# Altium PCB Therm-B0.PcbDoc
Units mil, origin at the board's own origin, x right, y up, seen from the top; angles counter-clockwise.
Board outline 1600 x 800 mil, 2 copper layers (Top Layer, Bottom Layer); 23 components, 22 nets, 79 pads, 19 vias.
Unrouted connection lines stored in the file: 16.
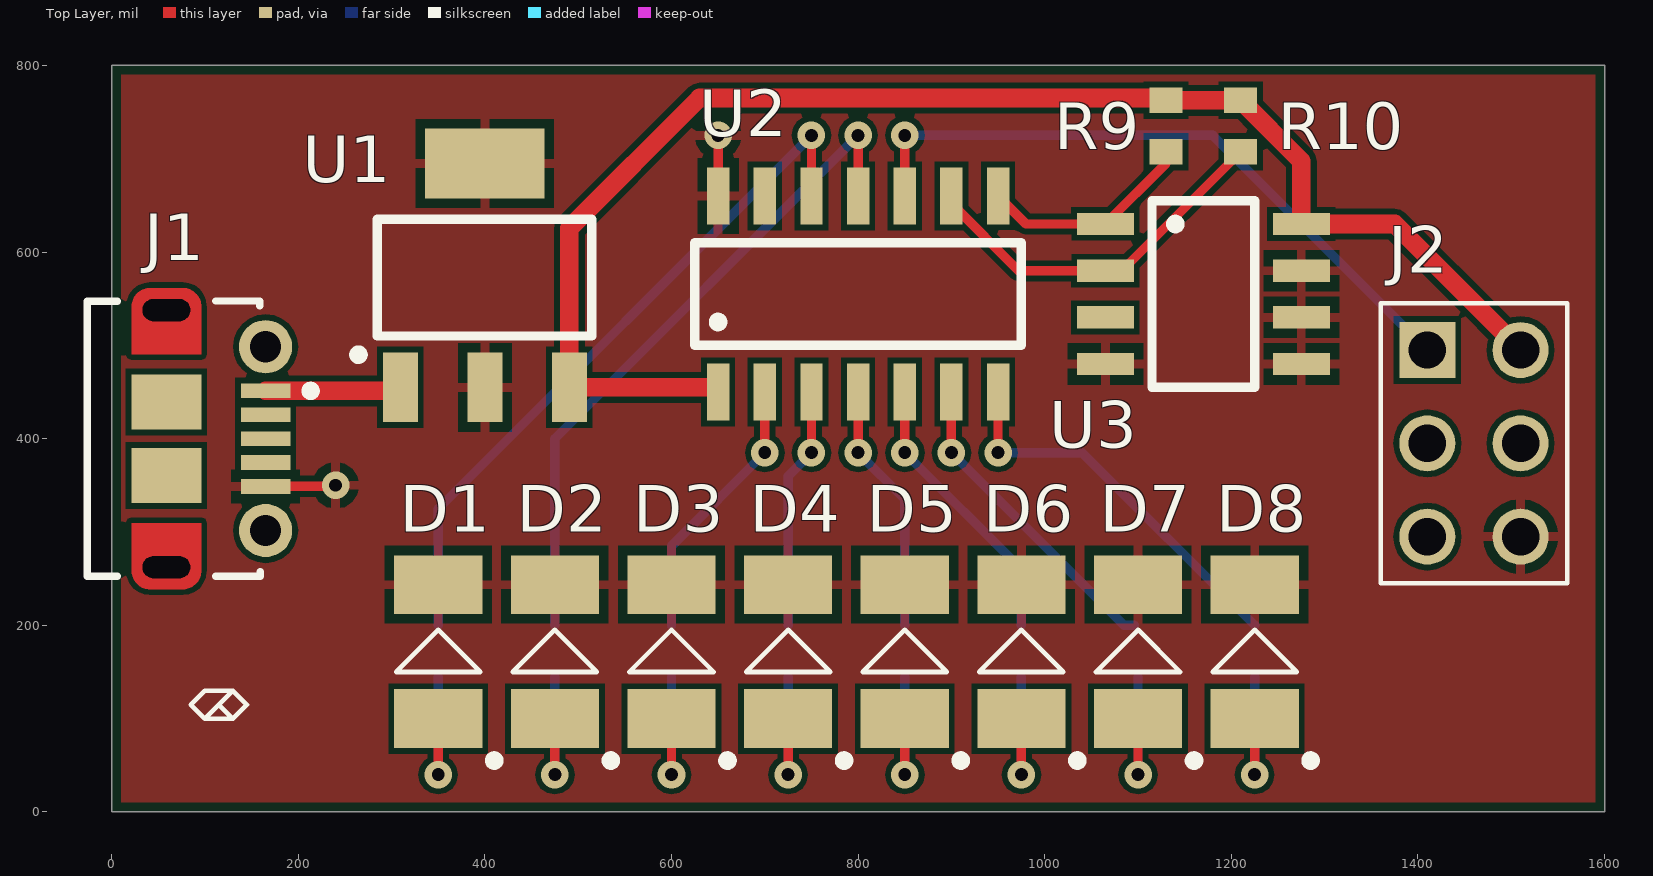
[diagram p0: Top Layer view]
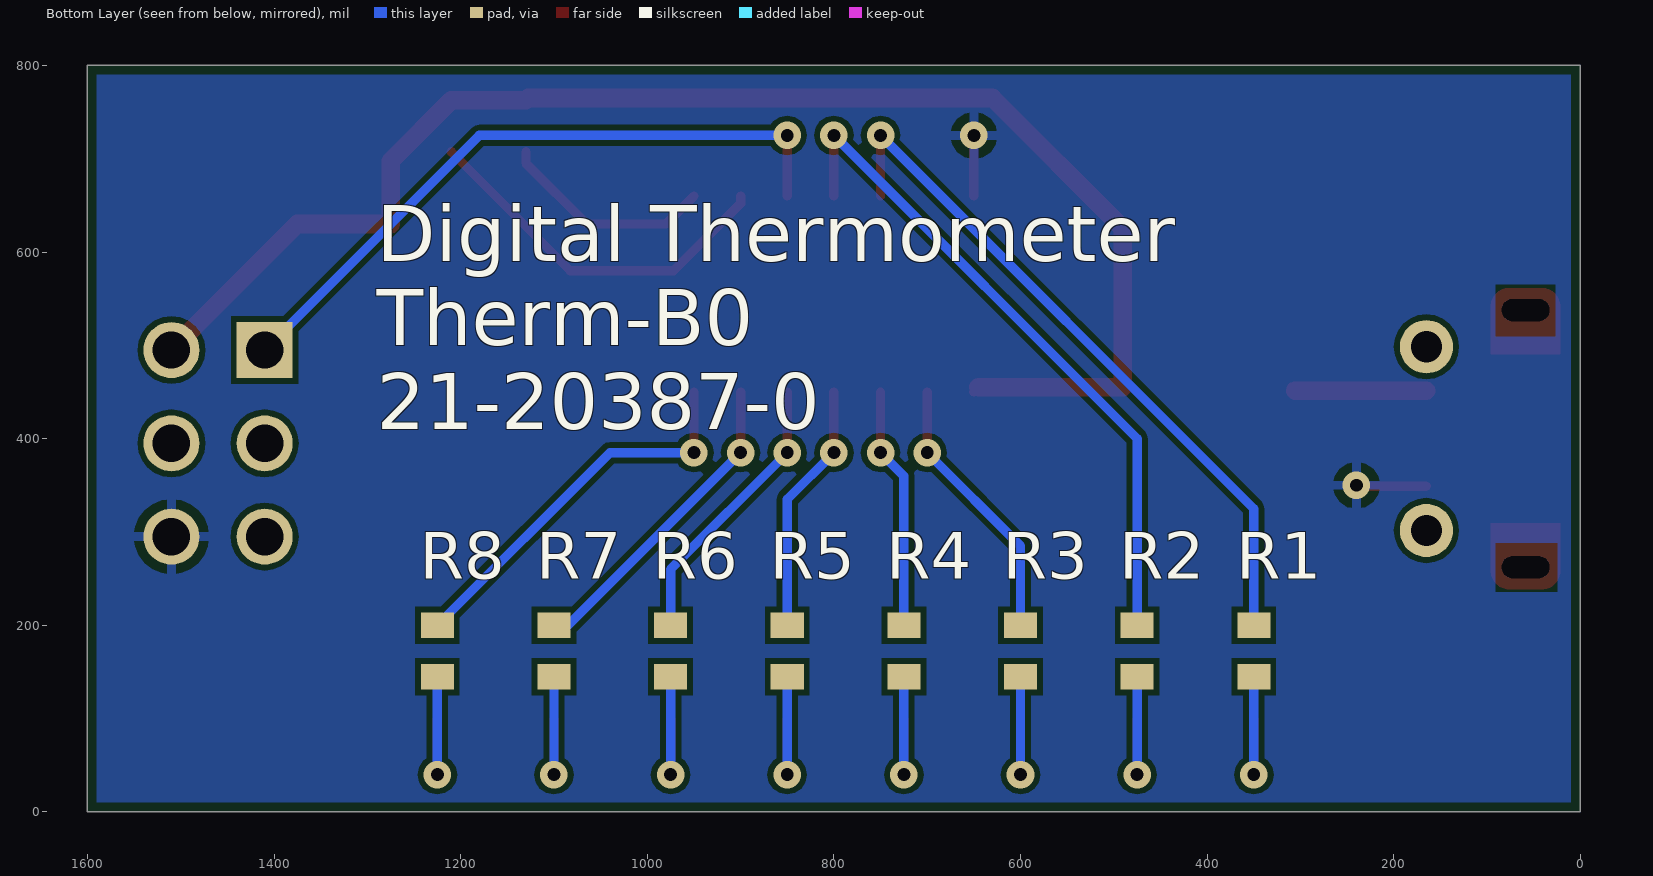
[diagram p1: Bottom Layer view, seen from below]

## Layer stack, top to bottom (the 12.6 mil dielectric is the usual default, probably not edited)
Top Solder: solder mask 0.4, Solder Resist, Dk 3.5
Top Layer: signal copper 1.4
Dielectric 1: dielectric 12.6, FR-4, Dk 4.8
Bottom Layer: signal copper 1.4
Bottom Solder: solder mask 0.4, Solder Resist, Dk 3.5

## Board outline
0,0 1600,0 1600,800 0,800

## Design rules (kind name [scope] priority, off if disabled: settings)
BoardOutlineClearance [All] p1: gap=10 ignorepadtopadclearanceinfootprint=FALSE except(0: Arc-SplitContinuation Track-SplitContinuation SMDPad-SplitContinuation THPad-SplitContinuation Via-SplitContinuation Fill-SplitContinuation Poly-SplitContinuation Region-SplitContinuation Text-SplitContinuation)
Clearance [All] p1: gap=6 ignorepadtopadclearanceinfootprint=FALSE except(0: Arc-Hole Track-Hole SMDPad-Hole THPad-Hole Via-Hole Fill-Hole Poly-Hole Region-Hole Text-Hole)
ComponentClearance [All] p1: gap=1 collisioncheckmode=3 verticalgap=1 showdistances=FALSE
PolygonConnect [All] p1: connectstyle=Relief reliefconductorwidth=10 reliefentries=4 polygonreliefangle="90 Angle" airgapwidth=10
RoutingVias [All] p1: holewidth=28 width=50 viastyle="Through Hole" minholewidth=13.78 minwidth=29.53 maxholewidth=28 maxwidth=29.53
SolderMaskExpansion [All] p1: expansion=4
Width [All] p1: maxlimit=20 minlimit=10 preferedwidth=10 minimp=50.000000 maximp=50.000000 favimp=50.000000
29 further rules are at their usual default settings.

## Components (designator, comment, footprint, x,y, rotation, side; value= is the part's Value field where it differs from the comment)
D1 "LED" LED 350,100 r90 top
D2 "LED" LED 475,100 r90 top
D3 "LED" LED 600,100 r90 top
D4 "LED" LED 725,100 r90 top
D5 "LED" LED 850,100 r90 top
D6 "LED" LED 975,100 r90 top
D7 "LED" LED 1100,100 r90 top
D8 "LED" LED 1225,100 r90 top
J1 "105017-0001" USB-MICRO-B_V 111.85,400 r270 top
J2 "Header" "2x3 Header Straight Pin ZigZag" 1410,495 r0 top
R1 "332" RESC1608X55X25NL10T15 350,172.44 r90 bottom
R2 "332" RESC1608X55X25NL10T15 475,172.44 r90 bottom
R3 "332" RESC1608X55X25NL10T15 600,172.44 r90 bottom
R4 "332" RESC1608X55X25NL10T15 725,172.44 r90 bottom
R5 "332" RESC1608X55X25NL10T15 850,172.44 r90 bottom
R6 "332" RESC1608X55X25NL10T15 975,172.44 r90 bottom
R7 "332" RESC1608X55X25NL10T15 1100,172.44 r90 bottom
R8 "332" RESC1608X55X25NL10T15 1225,172.44 r90 bottom
R9 "2k" RESC1608X55X25NL10T15 1130,735 r90 top
R10 "2k" RESC1608X55X25NL10T15 1210,735 r90 top
U1 "MCP1825S" SOT-223-3 309.5,455 r90 top
U2 "ATtiny404" "14-PIN SOIC 150" 650,450 r90 top
U3 "TMP75B-Q1" "8-Pin SOIC 150" 1065,630 r0 top

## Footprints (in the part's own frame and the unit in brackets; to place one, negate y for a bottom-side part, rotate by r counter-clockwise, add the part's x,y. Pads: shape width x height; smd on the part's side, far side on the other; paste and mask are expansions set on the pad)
"2x3 Header Straight Pin ZigZag" [mil]
  rect 60x60 hole 40: 1(0,0)
  round 60 hole 40: 2(100,0) 3(0,-100) 4(100,-100) 5(0,-200) 6(100,-200)
  silkscreen extent -50,-250 150,50
"8-Pin SOIC 150" [mil]
  rect 61x24 smd: 1(0,0) 2(0,-50) 3(0,-100) 4(0,-150) 5(210,-150) 6(210,-100) 7(210,-50) 8(210,0)
  silkscreen extent 50,-175 160,25
"14-PIN SOIC 150" [mil]
  rect 61x24 smd: 1(0,0) 2(0,-50) 3(0,-100) 4(0,-150) 5(0,-200) 6(0,-250) 7(0,-300) 8(210,-300) 9(210,-250) 10(210,-200) 11(210,-150) 12(210,-100) 13(210,-50) 14(210,0)
  silkscreen extent 50,-325 160,25
LED [mm]
  rect 1.6x2.4 smd: 1(0,0) 2(3.645,0)
  silkscreen extent -1.27,-1.65 2.41,1.14
RESC1608X55X25NL10T15 [mm] "Chip Resistor, 2-Leads, Body 1.60x0.80mm, IPC Medium Density"
  rect 0.7x0.9 smd: 1(-0.7,0) 2(0.7,0)
  body extent -0.85,-0.45 0.85,0.45, height 0.55
SOT-223-3 [mm]
  rect 1.9x0.95 smd: 1(0,0) 2(0,-2.299) 3(0,-4.597)
  rect 1.9x3.25 smd: 4(6.096,-2.299)
  silkscreen extent 0.76,-5.21 4.57,1.27
USB-MICRO-B_V [mm] "USB, MICRO B, Body 7.491x4.695 mm, Pitch 0.65 mm"
  rect 0.4x1.35 smd: 1(-1.3,1.35) 5(1.3,1.35)
  rect 0.4x1.35 smd mask+0.102: 2(-0.65,1.35) 3(0,1.35) 4(0.65,1.35)
  round 1.45 hole 0.85: 6(-2.5,1.35) 7(2.5,1.35)
  rrect50% 0x0 hole 0.6 slot 1.3 at 90 deg: 8(-3.5,-1.35) 11(3.5,-1.35)
  rect 1.5x1.9 smd: 9(-1,-1.35) 10(1,-1.35)
  Top Layer circle w0.5: c-3.6,-1.8 r0.25
  Top Layer circle w0.5: c-3.6,-0.9 r0.25
  Top Layer circle w0.5: c3.6,-1.8 r0.25
  Top Layer circle w0.5: c3.6,-0.9 r0.25
  Top Layer region: -3.6,-1.8 -3.6,-0.9 -4.1,-0.9 -4.1,-1.8
  Top Layer region: 3.6,-0.9 3.6,-1.8 4.1,-1.8 4.1,-0.9
  Top Layer region: 2.3,-0.4 2.3,-2.3 3.6,-2.3 3.6,-0.4
  Top Layer region: -2.3,-2.3 -2.3,-0.4 -3.6,-0.4 -3.6,-2.3
  silkscreen extent -3.75,-3.5 3.75,2.7, body extent -4.1,-3.9 4.1,1.5, height 2.67

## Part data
J1: library part CMP-2000-05827-1, "Micro-USB B Receptacle, Right Angle, Bottom Mount, Surface Mount, with Solder Tabs, -30 to 85 degC, 5-Pin USB, RoHS, Tape and Reel", Manufacturer=Molex, Package Description="5-Leads USB, Micro B, Body 7.5 x 5 mm, Pitch 0.65 mm", Package Reference=MICRO-B, Package Version="Rev. F, 12/2012", Standard Package=1, Voltage - Max=30V
J2: library part "2x3 Header Straight Pin ZigZag"
R1 R2 R3 R4 R5 R6 R7 R8: library part CMP-2000-04013-1, Manufacturer=Yageo, Part Number=RC0603FR-07332RL
R9 R10: library part CMP-2000-04259-1, Manufacturer=Yageo, Part Number=RC0603JR-072KL

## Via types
v1: diameter 29.53, hole 13.78, Top Layer to Bottom Layer, 19 vias

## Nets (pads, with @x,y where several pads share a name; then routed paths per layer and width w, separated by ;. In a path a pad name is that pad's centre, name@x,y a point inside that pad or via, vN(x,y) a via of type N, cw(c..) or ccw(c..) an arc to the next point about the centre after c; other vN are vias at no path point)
+3.3: J2.2 R9.2 R10.2 U1.3 U2.1 U3.8 | length 1566.1
  Top Layer w10: U2.1@645,455 U2.1 ; R9.2@1126.14,765 1128.38,761.52 R9.2@1129,760.56
  Top Layer w20: U2.1@645,455 U1.3 490.5,625.5 630,765 1126.14,765 1127.56,765 R9.2 R10.2 1275,697.56 U3.8 1375,630 J2.2
+5: J1.1 U1.1 | length 146.1
  Top Layer w10: U1.1@305.68,451.18 U1.1
  Top Layer w20: J1.1 U1.1@305.68,451.18
GND: D1.2 D2.2 D3.2 D4.2 D5.2 D6.2 D7.2 D8.2 J1.5 J2.6 U1.2 U1.4 U2.14 U3.4 U3.5 U3.6 U3.7 | length 140.5
  Top Layer w10: J1.5 238.82,348.82 v1(240,350) ; U2.14 v1(650,725)
LED1: R1.2 U2.12 | length 755.7
  Top Layer w10: U2.12 v1(750,725)
  Bottom Layer w10: R1.2 350,325 v1(750,725)
LED2: R2.2 U2.11 | length 724.6
  Top Layer w10: U2.11 v1(800,725)
  Bottom Layer w10: R2.2 475,400 v1(800,725)
LED3: R3.2 U2.2 | length 291.4
  Top Layer w10: v1(700,385) U2.2
  Bottom Layer w10: R3.2 600,285 v1(700,385)
LED4: R4.2 U2.3 | length 260.4
  Top Layer w10: v1(750,385) U2.3
  Bottom Layer w10: R4.2 725,360 v1(750,385)
LED5: R5.2 U2.4 | length 270.7
  Top Layer w10: v1(800,385) U2.4
  Bottom Layer w10: v1(800,385) 850,335 R5.2
LED6: R6.2 U2.5 | length 301.8
  Top Layer w10: v1(850,385) U2.5
  Bottom Layer w10: v1(850,385) 975,260 R6.2
LED7: R7.2 U2.6 | length 337.7
  Top Layer w10: v1(900,385) U2.6
  Bottom Layer w10: v1(900,385) 1085,200 R7.2@1096.06,200
LED8: R8.2 U2.7 | length 416.6
  Top Layer w10: v1(950,385) U2.7
  Bottom Layer w10: v1(950,385) 1040,385 R8.2
NetD1_1: D1.1 R1.1 | length 164.9
  Top Layer w10: v1(350,40) D1.1
  Bottom Layer w10: v1(350,40) R1.1
NetD2_1: D2.1 R2.1 | length 164.9
  Top Layer w10: v1(475,40) D2.1
  Bottom Layer w10: v1(475,40) R2.1
NetD3_1: D3.1 R3.1 | length 164.9
  Top Layer w10: v1(600,40) D3.1
  Bottom Layer w10: v1(600,40) R3.1
NetD4_1: D4.1 R4.1 | length 164.9
  Top Layer w10: v1(725,40) D4.1
  Bottom Layer w10: v1(725,40) R4.1
NetD5_1: D5.1 R5.1 | length 164.9
  Top Layer w10: v1(850,40) D5.1
  Bottom Layer w10: v1(850,40) R5.1
NetD6_1: D6.1 R6.1 | length 164.9
  Top Layer w10: v1(975,40) D6.1
  Bottom Layer w10: v1(975,40) R6.1
NetD7_1: D7.1 R7.1 | length 164.9
  Top Layer w10: v1(1100,40) D7.1
  Bottom Layer w10: v1(1100,40) R7.1
NetD8_1: D8.1 R8.1 | length 164.9
  Top Layer w10: v1(1225,40) D8.1
  Bottom Layer w10: v1(1225,40) R8.1
SCL: R10.1 U2.9 U3.2 | length 400.6
  Top Layer w10: U2.9 900,651.94 971.94,580 U3.2 1082.56,580 R10.1
SDA: R9.1 U2.8 U3.1 | length 231.8
  Top Layer w10: U2.8 980,630 U3.1 1130,695 R9.1
UPDI: J2.1 U2.10 | length 720.3
  Top Layer w10: U2.10 v1(850,725)
  Bottom Layer w10: v1(850,725) 1180,725 J2.1
pads on no net: J1.2 J1.3 J1.4 J1.6 J1.7 J1.8 J1.9 J1.10 J1.11 J2.3 J2.4 J2.5 U2.13 U3.3

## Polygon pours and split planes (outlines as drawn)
GND on Top Layer "Top Layer-GND" (solid, pour order 10): 0,800 0,0 1600,0 1600,800
GND on Bottom Layer "Bottom Layer-GND" (solid, pour order 14): 0,800 0,0 1600,0 1600,800

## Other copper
Bottom Layer:
  pour cut-out: 25,288 90.64,288 90.64,236 25,236
  pour cut-out: 26.76,262.2
  pour cut-out: 26.76,565 90.64,565 90.64,510 26.76,510
  pour cut-out: 58.7,510
  pour cut-out: 30,275
  pour cut-out: 55,455
  pour cut-out: 32.08,550.64

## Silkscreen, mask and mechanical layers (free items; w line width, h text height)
Top Overlay:
  lines w5: 100,100 85,115 100,130 130,130 ; 100,100 130,130 ; 100,100 115,115 130,100 ; 100,100 130,100 ; 130,100 145,115 130,130
Bottom Overlay:
  text "Digital Thermometer / Therm-B0 / 21-20387-0" at 1290,410 h60
Board Outline:
  the board outline again, w5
